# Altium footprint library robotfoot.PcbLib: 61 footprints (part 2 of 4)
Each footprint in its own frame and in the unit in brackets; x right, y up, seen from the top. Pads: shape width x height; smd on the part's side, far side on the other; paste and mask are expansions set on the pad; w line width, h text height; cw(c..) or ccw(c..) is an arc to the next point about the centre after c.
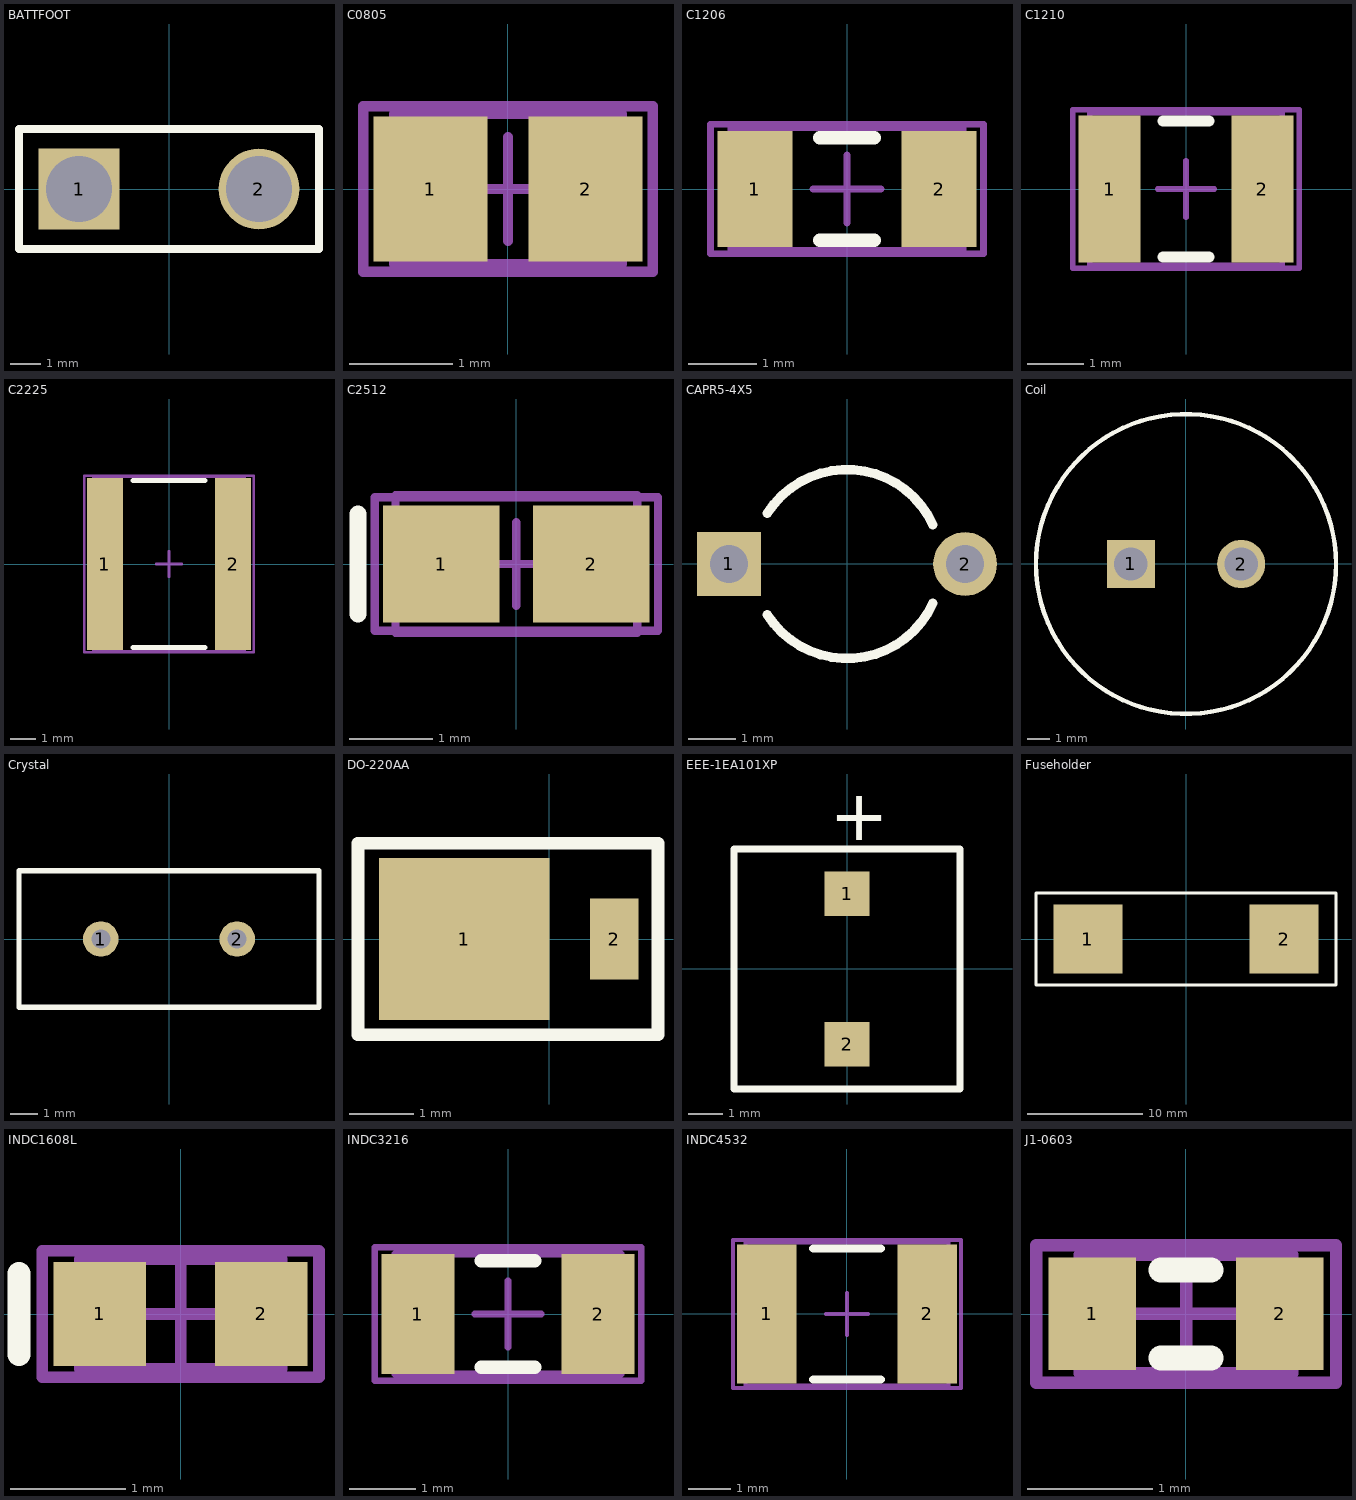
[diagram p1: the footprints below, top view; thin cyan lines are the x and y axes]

## BATTFOOT [mil]
pads (2):
  rect 106x106 hole 86: 1(-118.11,0)
  round 106 hole 86: 2(118.11,0)
Top Overlay:
  lines w10: -196.85,-78.74 -196.85,78.74 196.85,78.74 196.85,-78.74 -196.85,-78.74

## C0805 [mm] "Chip Capacitor, Body 2.0x1.3mm, IPC High Density"
height 1.4
pads (2):
  rect 1.1x1.4 smd: 1(-0.75,0) 2(0.75,0)
Mechanical 13:
  lines w0.1: -1.1,-0.725 1.1,-0.725 1.1,0.725 -1.1,0.725 -1.1,-0.725
Mechanical 15:
  lines w0.1: -0.5,0 0.5,0 ; 0,-0.5 0,0.5 ; -1.4,-0.8 1.4,-0.8 1.4,0.8 -1.4,0.8 -1.4,-0.8
3D body: height 1.4, standoff 0, extent -1.1,-0.725 1.1,0.725

## C1206 [mm] "Chip Capacitor, Body 3.2x1.6mm, IPC High Density"
height 1.3
pads (2):
  rect 1.1x1.7 smd: 1(-1.35,0) 2(1.35,0)
Top Overlay:
  lines w0.2: -0.4,-0.75 0.4,-0.75 ; -0.4,0.75 0.4,0.75
Mechanical 13:
  lines w0.1: -1.7,-0.9 -1.7,0.9 1.7,0.9 1.7,-0.9 -1.7,-0.9
Mechanical 15:
  lines w0.1: -0.5,0 0.5,0 ; 0,-0.5 0,0.5 ; -2,-0.95 -2,0.95 2,0.95 2,-0.95 -2,-0.95
3D body: height 1.3, standoff 0, extent -1.7,-0.9 1.7,0.9

## C1210 [mm] "Chip Capacitor, Body 3.2x2.5mm, IPC High Density"
height 1.3
pads (2):
  rect 1.1x2.6 smd: 1(-1.35,0) 2(1.35,0)
Top Overlay:
  lines w0.2: -0.4,-1.2 0.4,-1.2 ; -0.4,1.2 0.4,1.2
Mechanical 13:
  lines w0.1: -1.7,-1.35 1.7,-1.35 1.7,1.35 -1.7,1.35 -1.7,-1.35
Mechanical 15:
  lines w0.1: -0.5,0 0.5,0 ; 0,-0.5 0,0.5 ; -2,-1.4 2,-1.4 2,1.4 -2,1.4 -2,-1.4
3D body: height 1.3, standoff 0, extent -1.7,-1.35 1.7,1.35

## C2225 [mm] "Chip Capacitor, Body 5.7x6.4mm, IPC High Density"
height 1.4
pads (2):
  rect 1.4x6.7 smd: 1(-2.5,0) 2(2.5,0)
Top Overlay:
  lines w0.2: -1.4,-3.25 1.4,-3.25 ; -1.4,3.25 1.4,3.25
Mechanical 13:
  lines w0.1: -2.95,-3.4 -2.95,3.4 2.95,3.4 2.95,-3.4 -2.95,-3.4
Mechanical 15:
  lines w0.1: -0.5,0 0.5,0 ; 0,-0.5 0,0.5 ; -3.3,-3.45 -3.3,3.45 3.3,3.45 3.3,-3.45 -3.3,-3.45
3D body: height 1.4, standoff 0, extent -2.95,-3.4 2.95,3.4

## C2512 [mm] "Chip Capacitor, Body 2.54x1.27mm, IPC High Density"
height 1.3
pads (2):
  rect 1.4x1.4 smd: 1(-0.9,0) 2(0.9,0)
Top Overlay:
  lines w0.2: -1.9,-0.6 -1.9,0.6
Mechanical 13:
  lines w0.1: -1.45,-0.825 1.45,-0.825 1.45,0.825 -1.45,0.825 -1.45,-0.825
Mechanical 15:
  lines w0.1: -0.5,0 0.5,0 ; 0,-0.5 0,0.5 ; -1.7,-0.8 1.7,-0.8 1.7,0.8 -1.7,0.8 -1.7,-0.8
3D body: height 1.3, standoff 0, extent -1.45,-0.825 1.45,0.825

## CAPR5-4X5 [mm] "Capacitor; 2 Leads"
height 12
pads (2):
  rect 1.35x1.35 hole 0.8: 1(-2.5,0)
  round 1.35 hole 0.8: 2(2.5,0)
Top Overlay:
  lines w0.2: -1.687,-1.075 ccw(c0,0) 1.819,-0.832 ; -1.687,1.075 cw(c0,0) 1.819,0.832

## Coil [mil]
pads (2):
  rect 86x86 hole 59.5: 1(-98.43,0)
  round 86 hole 59.5: 2(98.43,0)
Top Overlay:
  circle w7.87: c0,0 r267.72

## Crystal [mm] "Crystal, Thru-Hole; 2 Leads"
height 8.2
pads (2):
  round 1.3 hole 0.7: 1(-2.5,0) 2(2.5,0)
Top Overlay:
  lines w0.2: -5.5,-2.5 -5.5,2.5 5.5,2.5 5.5,-2.5 -5.5,-2.5

## DO-220AA [mm]
pads (2):
  rect 2.67x2.54 smd: 1(-1.335,0)
  rect 0.762x1.27 smd: 2(1.016,0)
Top Overlay:
  lines w0.2: -3,-1.5 1.7,-1.5 1.7,1.5 -3,1.5 -3,-1.5

## EEE-1EA101XP [mm]
pads (2):
  rect 1.3x1.3 smd: 1(0,2.2) 2(0,-2.2)
Top Overlay:
  lines w0.2: -3.3,-3.5 -3.3,3.5 3.3,3.5 3.3,-3.5 -3.3,-3.5
  text "+" at -0.5,3.75 h1.5

## Fuseholder [mm]
pads (2):
  rect 6x6 smd: 1(-8.5,0) 2(8.5,0)
Top Overlay:
  lines w0.254: -13,-4 13,-4 13,4 -13,4 -13,-4

## INDC1608L [mm] "Chip Inductor, Body 1.6x0.8mm, IPC High Density"
height 0.55
pads (2):
  rect 0.8x0.9 smd: 1(-0.7,0) 2(0.7,0)
Top Overlay:
  lines w0.2: -1.4,-0.35 -1.4,0.35
Mechanical 13:
  lines w0.1: -0.875,-0.475 -0.875,0.475 0.875,0.475 0.875,-0.475 -0.875,-0.475
Mechanical 15:
  lines w0.1: -0.475,0 0.475,0 ; 0,-0.475 0,0.475 ; -1.2,-0.55 -1.2,0.55 1.2,0.55 1.2,-0.55 -1.2,-0.55
3D body: height 0.55, standoff 0, extent -0.875,-0.475 0.875,0.475

## INDC3216 [mm] "Chip Inductor, Body 3.2x1.6mm, IPC High Density"
height 0.55
pads (2):
  rect 1.1x1.8 smd: 1(-1.35,0) 2(1.35,0)
Top Overlay:
  lines w0.2: -0.4,-0.8 0.4,-0.8 ; -0.4,0.8 0.4,0.8
Mechanical 13:
  lines w0.1: -1.7,-0.9 -1.7,0.9 1.7,0.9 1.7,-0.9 -1.7,-0.9
Mechanical 15:
  lines w0.1: -0.5,0 0.5,0 ; 0,-0.5 0,0.5 ; -2,-1 -2,1 2,1 2,-1 -2,-1
3D body: height 0.55, standoff 0, extent -1.7,-0.9 1.7,0.9

## INDC4532 [mm] "Chip Inductor, Body 4.5x3.2mm, IPC High Density"
height 0.55
pads (2):
  rect 1.4x3.3 smd: 1(-1.9,0) 2(1.9,0)
Top Overlay:
  lines w0.2: -0.8,-1.55 0.8,-1.55 ; -0.8,1.55 0.8,1.55
Mechanical 13:
  lines w0.1: -2.4,-1.7 -2.4,1.7 2.4,1.7 2.4,-1.7 -2.4,-1.7
Mechanical 15:
  lines w0.1: -0.5,0 0.5,0 ; 0,-0.5 0,0.5 ; -2.7,-1.75 -2.7,1.75 2.7,1.75 2.7,-1.75 -2.7,-1.75
3D body: height 0.55, standoff 0, extent -2.4,-1.7 2.4,1.7

## J1-0603 [mm] "Chip Resistor, Body 1.6x0.8mm, IPC High Density"
height 0.9
pads (2):
  rect 0.7x0.9 smd: 1(-0.75,0) 2(0.75,0)
Top Overlay:
  lines w0.2: -0.2,-0.35 0.2,-0.35 ; -0.2,0.35 0.2,0.35
Mechanical 13:
  lines w0.1: -0.85,-0.475 -0.85,0.475 0.85,0.475 0.85,-0.475 -0.85,-0.475
Mechanical 15:
  lines w0.1: -0.475,0 0.475,0 ; 0,-0.475 0,0.475 ; -1.2,-0.55 -1.2,0.55 1.2,0.55 1.2,-0.55 -1.2,-0.55
3D body: height 0.9, standoff 0, extent -0.85,-0.475 0.85,0.475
